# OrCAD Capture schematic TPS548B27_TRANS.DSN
size E; title: TPS548B27 2.7-V to 16-V Input, 20-A Synchronous Buck Converter; rev: 1.0; note: Datasheet: SNVSBV3                              EVM: SNVU759; note: Synchronous Step Down Converter
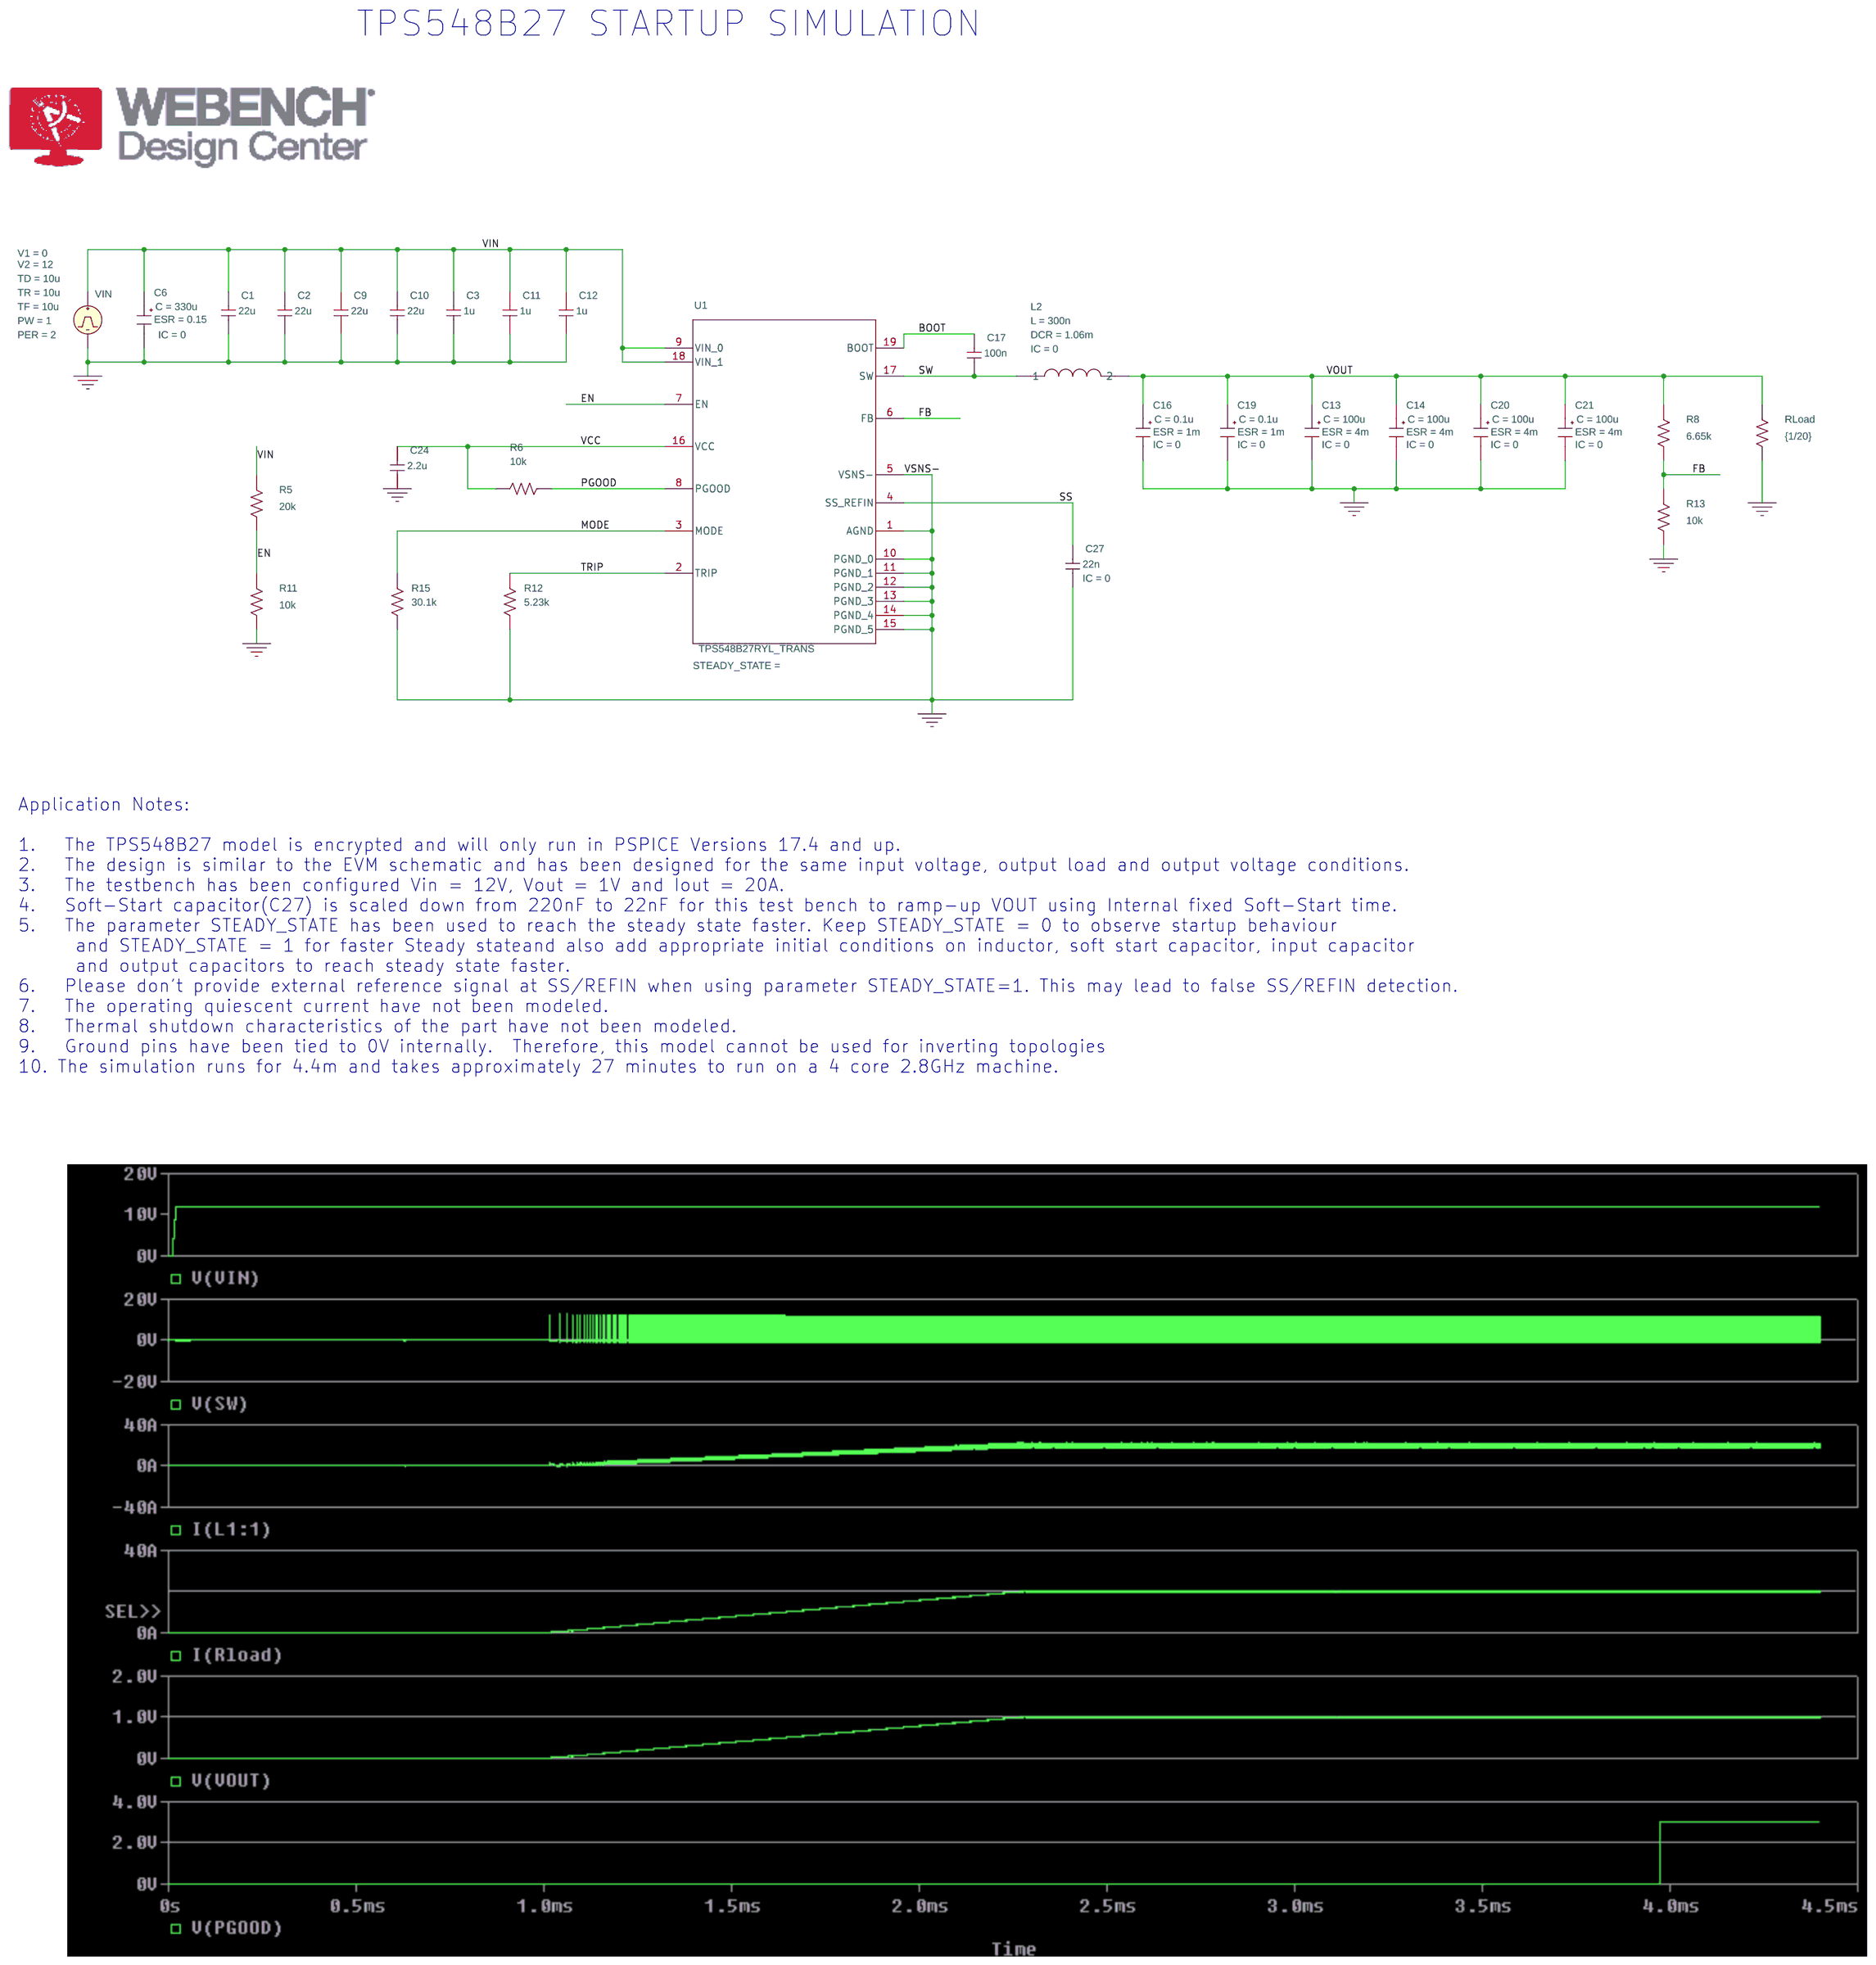
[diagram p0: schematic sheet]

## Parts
C1  22u  [RAD/CK05]
C2  22u  [RAD/CK05]
C3  1u  [RAD/CK05]
C6  CESR
C9  22u  [RAD/CK05]
C10  22u  [RAD/CK05]
C11  1u  [RAD/CK05]
C12  1u  [RAD/CK05]
C13  CESR
C14  CESR
C16  CESR
C17  100n  [RAD/CK05]
C19  CESR
C20  CESR
C21  CESR
C24  2.2u  [RAD/CK05]
C27  22n  [RAD/CK05]
L2  LDCR
R5  20k  [AX/RC05]
R6  10k  [AX/RC05]
R8  6.65k  [AX/RC05]
R11  10k  [AX/RC05]
R12  5.23k  [AX/RC05]
R13  10k  [AX/RC05]
R15  30.1k  [AX/RC05]
RLoad  {1/20}  [AX/RC05]
U1  TPS548B27RYL_TRANS  [RYL0019A-MFG]
VIN  VPULSE

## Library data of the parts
C1-C3 C9-C12 C17 = c_0
C6 = CESR_0: C: 330u; ESR: 0.15; IC: 0; PSpiceTemplate: X^@REFDES %IN %OUT @MODEL PARAMS:  ?C|C=@C||C=100u|  ?ESR|ESR=@ESR||ESR=0.01| ?X|X=@X||X=2|  ?IC|IC=@IC||IC=2|; X: 1
C13 C14 C20 C21 = CESR_0: C: 100u; ESR: 4m; IC: 0; PSpiceTemplate: X^@REFDES %IN %OUT @MODEL PARAMS:  ?C|C=@C||C=100u|  ?ESR|ESR=@ESR||ESR=0.01| ?X|X=@X||X=2|  ?IC|IC=@IC||IC=2|; X: 1
C16 C19 = CESR_0: C: 0.1u; ESR: 1m; IC: 0; PSpiceTemplate: X^@REFDES %IN %OUT @MODEL PARAMS:  ?C|C=@C||C=100u|  ?ESR|ESR=@ESR||ESR=0.01| ?X|X=@X||X=2|  ?IC|IC=@IC||IC=2|; X: 1
C24 = c_0: IC: 3
C27 = c_0: IC: 0
L2 = LDCR: DCR: 1.06m; IC: 0; L: 300n
R5 R6 R8 R11-R13 R15 RLoad = R
U1 = TPS548B27RYL_TRANS
VIN = VPULSE: PER: 2; PW: 1; TD: 10u; TF: 10u; TR: 10u; V1: 0; V2: 12

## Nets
VCC: C24.1 R6.2 U1.16(VCC)
VIN: C1.1 C2.1 C3.1 C6.1(IN) C9.1 C10.1 C11.1 C12.1 R5.1 U1.9(VIN_0) U1.18(VIN_1) VIN.1(+)
0: C1.2 C2.2 C3.2 C6.2(OUT) C9.2 C10.2 C11.2 C12.2 C13.2(OUT) C14.2(OUT) C16.2(OUT) C19.2(OUT) C20.2(OUT) C21.2(OUT) C24.2 C27.2 R11.2 R12.2 R13.2 R15.2 RLoad.2 U1.1(AGND) U1.5(VSNS-) U1.10(PGND_0) U1.11(PGND_1) U1.12(PGND_2) U1.13(PGND_3) U1.14(PGND_4) U1.15(PGND_5) VIN.2(-)
BOOT: C17.1 U1.19(BOOT)
EN: R5.2 R11.1 U1.7(EN)
FB: R8.2 R13.1 U1.6(FB)
MODE: R15.1 U1.3(MODE)
PGOOD: R6.1 U1.8(PGOOD)
SS: C27.1 U1.4(SS_REFIN)
SW: C17.2 L2.1 U1.17(SW)
TRIP: R12.1 U1.2(TRIP)
VOUT: C13.1(IN) C14.1(IN) C16.1(IN) C19.1(IN) C20.1(IN) C21.1(IN) L2.2 R8.1 RLoad.1

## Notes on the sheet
- TPS548B27 STARTUP SIMULATION
- Application Notes:
  1.   The TPS548B27 model is encrypted and will only run in PSPICE Versions 17.4 and up.
  2.   The design is similar to the EVM schematic and has been designed for the same input voltage, output load and output voltage conditions.
  3.   The testbench has been configured Vin = 12V, Vout = 1V and Iout = 20A.
  4.   Soft-Start capacitor(C27) is scaled down from 220nF to 22nF for this test bench to ramp-up VOUT using Internal fixed Soft-Start time.
  5.   The parameter STEADY_STATE has been used to reach the steady state faster. Keep STEADY_STATE = 0 to observe startup behaviour
        and STEADY_STATE = 1 for faster Steady stateand also add appropriate initial conditions on inductor, soft start capacitor, input capacitor
        and output capacitors to reach steady state faster.
  6.   Please don't provide external reference signal at SS/REFIN when using parameter STEADY_STATE=1. This may lead to false SS/REFIN detection.
  7.   The operating quiescent current have not been modeled.
  8.   Thermal shutdown characteristics of the part have not been modeled.
  9.   Ground pins have been tied to 0V internally.  Therefore, this model cannot be used for inverting topologies
  10. The simulation runs for 4.4m and takes approximately 27 minutes to run on a 4 core 2.8GHz machine.
